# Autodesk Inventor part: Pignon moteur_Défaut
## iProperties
Shininess: 64.0
Length Units: 11269
Angle Units: 11279
Time Units: 11290
Mass Units: 11283
Length Display Precision: 3
Angle Display Precision: 2
Compacted: True
Part Number: Pignon moteur_Défaut
Document SubType Name: Modeling
Created: 2006-01
Material: Par défaut
Designer: Fricot
Density: 0.0
Volumn: 0.0
Area: 0.0
PropertySet Name: Model Information
Control State: 0
Master: False
Checked Out: False
Author: Fricot
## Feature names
1. Base1
